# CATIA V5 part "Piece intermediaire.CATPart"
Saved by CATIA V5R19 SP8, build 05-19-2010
Part number: Piece intermediaire
Property "Entraxe pièce intermédiaire": 350 mm
Publications: "Entraxe pièce intermédiare"
Bounding box of the stored display mesh (mm): x -150 to 150, y -149.807 to 489.807, z -300 to 300
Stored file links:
  C:\Users\rcousturie\Desktop\EU_thinkMotion\iao\IAO_MMS_Groupe1\flacan\flacan\flacan\Piece intermediaire.CATPart
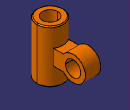
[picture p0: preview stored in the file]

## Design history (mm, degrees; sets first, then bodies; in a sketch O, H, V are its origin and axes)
Parameters
  `Entraxe pièce intermédiare` = 350 mm
Body1 (main body)
  Sketch1 on yz-plane, origin (0, 0, 0), H (0, 1, 0), V (0, 0, 1)
    arc A1 centre (350, 0) radius 140 from (240.7125, -87.5) to (240.7125, 87.5) ccw
    point P1 (350, 0)
    line L1 (240.7125, 87.5) -> (0, 87.5)
    line L2 (0, 87.5) -> (0, -87.5)
    line L3 (0, -87.5) -> (240.7125, -87.5)
    reference intersected line E1 through (0, 0) direction (0, 1) from zx-plane
    radius A1 = 140
    distance P1 V = 350 {= `Entraxe pièce intermédiare`}
    distance P1 H = 0
    distance L1 H = 87.5
    distance L2 E1 = 0
    distance L3 L1 = 175
    horizontal: L1 H
  Pad1: profile Sketch1, direction (1, 0, 0), length 87.5, opposite side length 87.5
  Sketch2 on xy-plane, origin (0, 0, 0), H (1, 0, 0), V (0, 1, 0)
    circle A1 centre (0, 0) radius 150
    radius A1 = 150
  Pad2: profile Sketch2, direction (0, 0, 1), length 300, opposite side length 300
  Sketch3 on end face of Pad1, origin (87.5, 0, 0), H (0, 1, 0), V (0, 0, 1)
    circle A1 centre (350, 0) radius 87.5
    point P1 (350, 0)
    reference projected line E1 through (0, 0) direction (0, 1) from axis of face of Pad2 from Sketch2.A1
    radius A1 = 87.5
    distance P1 H = 0
    distance P1 E1 = 350
  Pocket1: profile Sketch3, direction (-1, 0, 0), through (limit type 6)
  Sketch4 on end face of Pad2, origin (0, 0, 300), H (1, 0, 0), V (0, 1, 0)
    circle A1 centre (0, 0) radius 87.5
    point P1 (0, 0)
    radius A1 = 87.5
    distance P1 O = 0
  Pocket2: profile Sketch4, direction (0, 0, -1), through (limit type 6)
  Chamfer1: length 10, angle 45, on edge [face of Pad2 from Sketch2.A1 | end face of Pad2]; edge [start face of Pad2 | face of Pad2 from Sketch2.A1]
